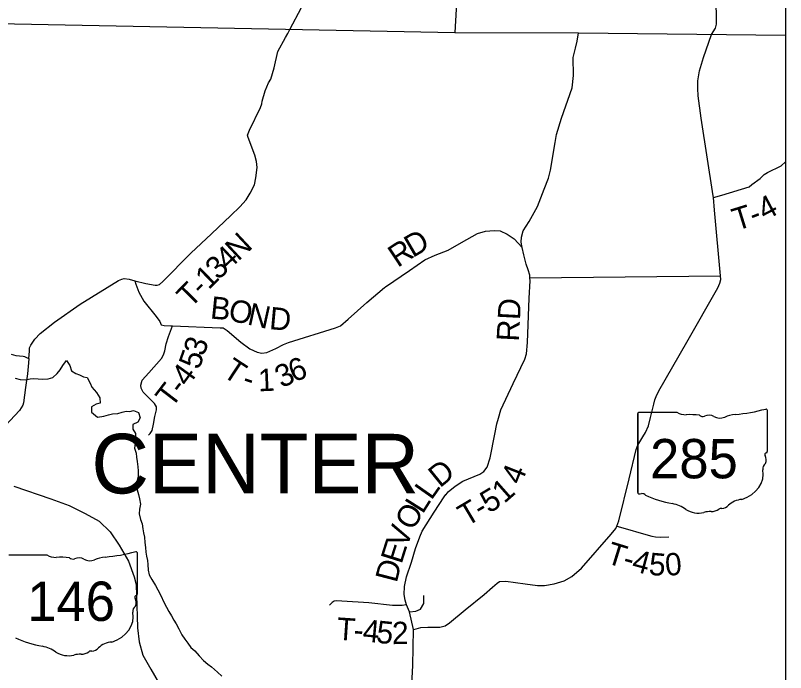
# Model space of a CAD drawing. Extents: x -22 to 431, y -18 to 160.
# Drawn here: x -3.877 to -1.919, y 15.371 to 17.042 of the extents above; entities that cross this region are included whole.
import ezdxf

# ---------------------------------------------------------------- set-up
doc = ezdxf.new("R2010")
doc.units = 0
for name, color, linetype in [('GM_X_Adjacent_County_Text', 7, 'Continuous'), ('GM_X_Airport_Location_Class_2', 7, 'Continuous'), ('GM_X_City_Street_Text', 7, 'Continuous'), ('GM_X_County_Road', 7, 'Continuous'), ('GM_X_County_Road_Text', 7, 'Continuous'), ('GM_X_Major_River_Text', 7, 'Continuous'), ('GM_X_Minor_River', 7, 'Continuous'), ('GM_X_Minor_River_Text', 7, 'Continuous'), ('GM_X_Rail_Line', 7, 'Continuous'), ('GM_X_Section', 7, 'Continuous')]:
    doc.layers.add(name, color=color, linetype=linetype)

msp = doc.modelspace()

# ---------------------------------------------------------------- linework, layer by layer
at = {"layer": 'GM_X_Adjacent_County_Text'}
msp.add_lwpolyline([(-3.888, 16.1801), (-3.8762, 16.1772), (-3.8568, 16.1754), (-3.8538, 16.1747), (-3.8485, 16.1717), (-3.8431, 16.1694), (-3.8434, 16.158), (-3.8466, 16.1307), (-3.8513, 16.0957), (-3.8563, 16.0566), (-3.8578, 16.0505), (-3.8664, 16.0371), (-3.9018, 15.9989)], dxfattribs=at)
at = {"layer": 'GM_X_Airport_Location_Class_2'}
for p, q in [((-1.9656, 16.0375), (-1.9656, 15.9328)), ((-2.2951, 16.0291), (-2.2951, 15.829)), ((-2.2951, 15.829), (-2.2951, 16.0291)), ((-2.2951, 15.829), (-2.2951, 16.0291)), ((-2.2919, 16.0325), (-2.1954, 16.0325)), ((-1.9656, 15.9328), (-1.9656, 15.9328)), ((-3.8933, 15.6699), (-3.7968, 15.6699)), ((-3.567, 15.6749), (-3.567, 15.5702)), ((-3.567, 15.5702), (-3.567, 15.5702))]:
    msp.add_line(p, q, dxfattribs=at)
for centre, major_axis, start_param, end_param in [((-2.083, 16.3054), (0.3495, 0), 4.814394, 5.042369), ((-1.9692, 16.0379), (0.00367, 0), 6.141152, 7.989035), ((-2.2914, 16.0295), (0.00382, 0), 1.712693, 3.28349), ((-2.1724, 16.0558), (0.037, 0), 4.042523, 4.731795), ((-2.1601, 15.9202), (0.133, 0), 1.404758, 1.657858), ((-2.1299, 16.0306), (0.0107, 0), 3.836095, 5.185415), ((-2.1142, 16.0074), (0.0222, 0), 0.950623, 2.079405), ((-2.0856, 16.0392), (0.0267, 0), 4.081561, 5.145723), ((-2.0384, 15.9714), (0.0703, 0), 1.699011, 2.107814), ((-1.9664, 15.9251), (0.00568, 0), 1.883978, 3.671073), ((-2.0025, 15.9119), (0.0341, 0), 5.934695, 6.695948), ((-1.9695, 15.9324), (0.00393, 0), 5.05454, 6.418171), ((-1.9524, 15.889), (0.0248, 0), 2.387724, 3.262537), ((-2.0634, 15.8757), (0.0874, 0), 5.101752, 6.440018), ((-2.2913, 15.8285), (0.00385, 0), 3.00124, 4.508301), ((-2.2907, 15.849), (0.0294, 0), 4.665946, 4.897461), ((-2.2847, 15.8174), (0.0106, 0), 0.519207, 1.627899), ((-2.1509, 15.9972), (0.2524, 0), 4.195997, 4.488961), ((-2.2262, 15.7391), (0.079, 0), 0.823519, 1.323587), ((-2.0265, 15.7728), (0.0479, 0), 1.647645, 2.488434), ((-2.1407, 15.8164), (0.0501, 0), 4.026481, 4.996735), ((-2.1118, 15.7473), (0.0412, 0), 1.495662, 1.94098), ((-2.1081, 15.8015), (0.0267, 0), 4.691044, 5.507374), ((-2.084, 15.7821), (0.00752, 0), 1.147584, 2.315152), ((-2.0872, 15.8096), (0.0282, 0), 4.937069, 5.64225), ((-3.7738, 15.6932), (0.037, 0), 4.042523, 4.731795), ((-3.7615, 15.5576), (0.133, 0), 1.404758, 1.657858), ((-3.7313, 15.668), (0.0107, 0), 3.836095, 5.185415), ((-3.7156, 15.6448), (0.0222, 0), 0.950623, 2.079405), ((-3.6398, 15.6088), (0.0703, 0), 1.699011, 2.107814), ((-3.6844, 15.9428), (0.3495, 0), 4.814394, 5.042369), ((-3.5706, 15.6753), (0.00367, 0), 6.141152, 7.989035), ((-3.687, 15.6765), (0.0267, 0), 4.081561, 5.145723), ((-3.5678, 15.5625), (0.00568, 0), 1.883978, 3.671073), ((-3.5709, 15.5698), (0.00393, 0), 5.05454, 6.418171), ((-3.6039, 15.5493), (0.0341, 0), 5.934695, 6.695948), ((-3.5538, 15.5264), (0.0248, 0), 2.387724, 3.262537), ((-3.6648, 15.5131), (0.0874, 0), 5.101752, 6.440018), ((-3.7523, 15.6346), (0.2524, 0), 4.195997, 4.488961), ((-3.6279, 15.4102), (0.0479, 0), 1.647645, 2.488434), ((-3.8276, 15.3765), (0.079, 0), 0.823519, 1.323587), ((-3.6886, 15.447), (0.0282, 0), 4.937069, 5.64225), ((-3.7421, 15.4538), (0.0501, 0), 4.026481, 4.996735), ((-3.7132, 15.3846), (0.0412, 0), 1.495662, 1.94098), ((-3.7095, 15.4388), (0.0267, 0), 4.691044, 5.507374), ((-3.6854, 15.4195), (0.00752, 0), 1.147584, 2.315152)]:
    msp.add_ellipse(centre, major_axis=major_axis, ratio=0.8, start_param=start_param, end_param=end_param, dxfattribs=at)
at = {"layer": 'GM_X_County_Road'}
msp.add_lwpolyline([(-2.5693, 16.3746), (-2.0844, 16.3793)], dxfattribs=at)
at = {"layer": 'GM_X_Major_River_Text'}
for p, q in [((-2.7468, 17.2227), (-2.7601, 16.9978)), ((-4.7644, 17.0381), (-2.7601, 16.9978)), ((-2.7601, 16.9978), (-2.4458, 16.9972)), ((-2.4458, 16.9972), (-1.9192, 16.991))]:
    msp.add_line(p, q, dxfattribs=at)
at = {"layer": 'GM_X_Minor_River'}
for points in [[(-3.8776, 16.1191), (-3.8647, 16.1158), (-3.8525, 16.1152), (-3.8397, 16.1176), (-3.8299, 16.1188), (-3.8189, 16.1174), (-3.8075, 16.1168), (-3.7939, 16.1177), (-3.7818, 16.1212), (-3.7705, 16.1312), (-3.7634, 16.1407), (-3.7564, 16.1518), (-3.7474, 16.164), (-3.7386, 16.1512)], [(-3.7386, 16.1512), (-3.7343, 16.1376), (-3.7236, 16.1309), (-3.7137, 16.128), (-3.7042, 16.1231), (-3.6947, 16.1213), (-3.6866, 16.107), (-3.6823, 16.0964), (-3.6712, 16.0825), (-3.6627, 16.0693), (-3.6618, 16.056), (-3.6717, 16.0529), (-3.6833, 16.0467), (-3.6832, 16.033), (-3.6683, 16.0203), (-3.6524, 16.0227), (-3.64, 16.0263), (-3.6298, 16.0286), (-3.6169, 16.0299), (-3.6056, 16.0331), (-3.5957, 16.0351), (-3.5863, 16.0348), (-3.5764, 16.0368), (-3.5643, 16.0323), (-3.5596, 16.0183), (-3.5659, 16.0077), (-3.5784, 16.0015), (-3.5786, 15.9901), (-3.5713, 15.9788), (-3.5708, 15.9636), (-3.5729, 15.9541), (-3.5739, 15.9416), (-3.5696, 15.9287), (-3.5688, 15.9185), (-3.5675, 15.9071), (-3.5659, 15.8942), (-3.565, 15.8836), (-3.5649, 15.8699), (-3.5678, 15.8593), (-3.5703, 15.8445), (-3.564, 15.8233), (-3.5616, 15.8123), (-3.5592, 15.7987), (-3.5617, 15.7861), (-3.5627, 15.7743), (-3.5592, 15.7599), (-3.5549, 15.7494), (-3.5529, 15.7365), (-3.5513, 15.7263), (-3.5492, 15.7149), (-3.5476, 15.7012), (-3.5463, 15.6887), (-3.5454, 15.677), (-3.5438, 15.6668), (-3.5414, 15.6561), (-3.5402, 15.6455), (-3.5393, 15.6315), (-3.5365, 15.619), (-3.5303, 15.6073), (-3.5207, 15.5918), (-3.5153, 15.5813), (-3.5068, 15.565), (-3.5002, 15.5518), (-3.4925, 15.5375), (-3.4867, 15.5265), (-3.4801, 15.5148), (-3.474, 15.5043), (-3.4682, 15.4945), (-3.4612, 15.482), (-3.4535, 15.4669), (-3.4462, 15.4556), (-3.4389, 15.4458), (-3.4308, 15.4345), (-3.4205, 15.4263), (-3.4094, 15.4138), (-3.3987, 15.4018), (-3.388, 15.3924), (-3.3784, 15.3853), (-3.3635, 15.3718), (-3.3524, 15.3613)]]:
    msp.add_lwpolyline(points, dxfattribs=at)
at = {"layer": 'GM_X_Minor_River_Text'}
for points in [[(-3.1848, 16.9959), (-3.1793, 17.0062), (-3.1497, 17.0618), (-3.075, 17.216), (-3.0391, 17.2815), (-3.0388, 17.2822)], [(-3.5737, 16.3665), (-3.5456, 16.3598), (-3.5213, 16.3562), (-3.5164, 16.3562), (-3.5103, 16.3578), (-3.502, 16.3647), (-3.4312, 16.4373), (-3.3788, 16.4863), (-3.3291, 16.5325), (-3.3065, 16.5547), (-3.2903, 16.5727), (-3.2798, 16.5894), (-3.2694, 16.6112), (-3.2657, 16.6286), (-3.2628, 16.6549), (-3.2641, 16.6704), (-3.268, 16.6859), (-3.285, 16.7314), (-3.287, 16.7374), (-3.2821, 16.7496), (-3.2541, 16.8075), (-3.2504, 16.817), (-3.2497, 16.8235), (-3.2423, 16.8497), (-3.2333, 16.8703), (-3.2277, 16.8798), (-3.2188, 16.9083), (-3.21, 16.9498), (-3.1905, 16.9852), (-3.1848, 16.9959)], [(-2.5891, 16.4516), (-2.5911, 16.4648), (-2.5905, 16.4777), (-2.586, 16.4941), (-2.571, 16.5177), (-2.5501, 16.5558), (-2.5329, 16.6), (-2.5221, 16.6278), (-2.517, 16.6479), (-2.505, 16.7186), (-2.5013, 16.7391), (-2.4887, 16.7802), (-2.4616, 16.8575), (-2.458, 16.8886), (-2.4591, 16.9345), (-2.4533, 16.9584), (-2.449, 16.9759), (-2.4458, 16.9972)], [(-2.1027, 16.5788), (-2.0814, 16.585), (-2.0121, 16.6059), (-2.0049, 16.6113), (-1.9838, 16.627), (-1.974, 16.637), (-1.965, 16.6423), (-1.9306, 16.6589), (-1.9192, 16.6694)], [(-2.9363, 16.3515), (-2.9361, 16.3517), (-2.8751, 16.393), (-2.8359, 16.4198), (-2.8102, 16.4318), (-2.7769, 16.4449), (-2.7433, 16.4641), (-2.7024, 16.4868), (-2.6824, 16.493), (-2.6596, 16.4947), (-2.6445, 16.4937), (-2.6266, 16.4855), (-2.609, 16.4734), (-2.5891, 16.4516)], [(-2.7825, 15.8234), (-2.7823, 15.8236), (-2.7765, 15.8302), (-2.7592, 15.8448), (-2.7396, 15.8571), (-2.6965, 15.8752), (-2.6863, 15.8821), (-2.6776, 15.8928), (-2.6698, 15.9172), (-2.6581, 15.9769), (-2.653, 16.0035), (-2.6489, 16.0176), (-2.643, 16.0389), (-2.6113, 16.1059), (-2.5821, 16.1676), (-2.5777, 16.1813), (-2.5756, 16.2102), (-2.5708, 16.3226), (-2.5688, 16.367), (-2.5693, 16.3746), (-2.5697, 16.3811), (-2.5736, 16.3947), (-2.579, 16.4095), (-2.5848, 16.4326), (-2.5891, 16.4516)], [(-3.8431, 16.1694), (-3.841, 16.1884), (-3.841, 16.1964), (-3.8381, 16.2033), (-3.8276, 16.2185), (-3.8136, 16.2327), (-3.7774, 16.2618), (-3.7121, 16.3074), (-3.6151, 16.3673), (-3.6067, 16.3712), (-3.6007, 16.3727), (-3.5874, 16.3713), (-3.5737, 16.3665)], [(-3.5737, 16.3665), (-3.5706, 16.3585), (-3.5636, 16.3384), (-3.5502, 16.315), (-3.5192, 16.2765), (-3.51, 16.2633), (-3.5065, 16.2546), (-3.4989, 16.2535), (-3.482, 16.2524)], [(-3.482, 16.2524), (-3.4776, 16.2521), (-3.3566, 16.2476), (-3.349, 16.2473), (-3.3387, 16.2409), (-3.3036, 16.2112), (-3.2807, 16.1943), (-3.2621, 16.1857), (-3.2507, 16.1831), (-3.2382, 16.1847), (-3.2151, 16.1951), (-3.1958, 16.2047), (-3.183, 16.2101), (-3.063, 16.2474), (-3.0509, 16.2528), (-3.0313, 16.2693), (-2.9838, 16.3117), (-2.9386, 16.35), (-2.9363, 16.3515)], [(-3.539, 15.9745), (-3.5344, 15.9783), (-3.5296, 15.9863), (-3.5259, 16.0027), (-3.5226, 16.0221), (-3.5182, 16.0392), (-3.5183, 16.0468), (-3.5232, 16.0547), (-3.5519, 16.0841), (-3.5573, 16.0936), (-3.5585, 16.1012), (-3.5548, 16.1141), (-3.5379, 16.1325), (-3.5059, 16.1691), (-3.5003, 16.179), (-3.4969, 16.1886), (-3.4936, 16.2068), (-3.4881, 16.2251), (-3.4776, 16.2521)], [(-2.8646, 15.4806), (-2.875, 15.5254), (-2.8829, 15.5432), (-2.886, 15.5553), (-2.8888, 15.5693), (-2.8882, 15.5894), (-2.8827, 15.6145), (-2.8704, 15.6519), (-2.8601, 15.6861), (-2.8489, 15.7162), (-2.8426, 15.7307), (-2.8122, 15.7787), (-2.7874, 15.8176), (-2.7825, 15.8234)], [(-2.3484, 15.7427), (-2.3271, 15.737), (-2.2807, 15.7236), (-2.259, 15.7177), (-2.2499, 15.7159), (-2.2362, 15.7148), (-2.2158, 15.7161)], [(-2.875, 15.5254), (-2.8593, 15.5273), (-2.8473, 15.5324), (-2.8388, 15.5461), (-2.8388, 15.5665)], [(-2.8829, 15.5432), (-2.8935, 15.5412), (-2.9019, 15.5411), (-2.9182, 15.5414), (-2.9782, 15.5482), (-3.0476, 15.5522), (-3.0609, 15.5529), (-3.0666, 15.5521), (-3.0715, 15.549), (-3.0787, 15.5418)]]:
    msp.add_lwpolyline(points, dxfattribs=at)
at = {"layer": 'GM_X_Rail_Line'}
for points in [[(-2.8698, 15.3253), (-2.8669, 15.3886), (-2.8646, 15.4806), (-2.8582, 15.4822), (-2.8461, 15.4857), (-2.8286, 15.4866), (-2.7979, 15.4864), (-2.7915, 15.4876), (-2.7846, 15.4895), (-2.7733, 15.4976), (-2.7334, 15.5305), (-2.6855, 15.5696), (-2.6644, 15.5884), (-2.6527, 15.5979), (-2.6463, 15.6022), (-2.6307, 15.603), (-2.581, 15.5965), (-2.5498, 15.5922), (-2.5324, 15.592), (-2.5074, 15.5963), (-2.482, 15.6041), (-2.4627, 15.6152), (-2.4379, 15.6359), (-2.3626, 15.7226), (-2.351, 15.7375), (-2.3484, 15.7427), (-2.3428, 15.757), (-2.317, 15.8638), (-2.299, 15.938), (-2.2949, 15.9487), (-2.29, 15.9578), (-2.2818, 15.9704), (-2.2754, 15.9815), (-2.2675, 15.9982), (-2.2624, 16.0192), (-2.2543, 16.053), (-2.2517, 16.064), (-2.2484, 16.0724), (-2.2413, 16.0873), (-2.1701, 16.2108), (-2.0914, 16.3488), (-2.0866, 16.3609), (-2.084, 16.3701), (-2.0844, 16.3793), (-2.0997, 16.5465), (-2.1027, 16.5788), (-2.103, 16.5825), (-2.1336, 16.7805), (-2.1413, 16.837), (-2.1425, 16.8559), (-2.1419, 16.8749), (-2.1379, 16.9007), (-2.1276, 16.9342), (-2.1078, 16.9932), (-2.0974, 17.0092), (-2.0948, 17.0191), (-2.0945, 17.0301), (-2.0971, 17.1815)], [(-3.8813, 15.8449), (-3.787, 15.8126), (-3.74, 15.7954), (-3.6994, 15.7752), (-3.6638, 15.756), (-3.6357, 15.7287), (-3.6135, 15.6948), (-3.5898, 15.6545), (-3.5751, 15.6141), (-3.5702, 15.5944), (-3.5686, 15.5397), (-3.5675, 15.5146), (-3.5663, 15.4846), (-3.5623, 15.4489), (-3.5531, 15.4149), (-3.5328, 15.3795), (-3.5105, 15.341), (-3.4543, 15.2891), (-3.3469, 15.2432), (-3.2812, 15.216), (-3.2811, 15.216)]]:
    msp.add_lwpolyline(points, dxfattribs=at)
at = {"layer": 'GM_X_Section'}
msp.add_line((-1.9192, 20.9345), (-1.9192, 14.1345), dxfattribs=at)

# ---------------------------------------------------------------- texts
at = {"layer": 'GM_X_Airport_Location_Class_2'}
for s, p in [('285', (-2.2637, 15.8647)), ('146', (-3.847, 15.5021))]:
    msp.add_text(s, height=0.1, dxfattribs=at).set_placement(p)
at = {"layer": 'GM_X_City_Street_Text'}
for s, height, rotation, p in [('4', 0.0568, 27.7307, (-1.9717, 16.5189)), ('T', 0.0568, 17.2341, (-2.0445, 16.4936)), ('-', 0.0568, 21.2035, (-1.9999, 16.5076)), ('N', 0.0568, 43.1296, (-3.3106, 16.4152)), ('D', 0.0568, 30.2478, (-2.867, 16.4246)), ('R', 0.0568, 33.506, (-2.9052, 16.3993)), ('4', 0.0568, 43.3954, (-3.3359, 16.3912)), ('3', 0.0568, 44.0616, (-3.361, 16.3669)), ('1', 0.0568, 44.5879, (-3.3858, 16.3425)), ('T', 0.0568, 45.6182, (-3.4318, 16.2957)), ('-', 0.0568, 45.276, (-3.4021, 16.326)), ('B', 0.0568, 354.2335, (-3.3832, 16.2713)), ('O', 0.0568, 347.6727, (-3.3385, 16.2669)), ('N', 0.0568, 347.5648, (-3.2897, 16.2562)), ('RD', 0.05682, 87.0641, (-2.5972, 16.2116)), ('D', 0.0568, 354.853, (-3.2331, 16.2442)), ('3', 0.0568, 71.3433, (-3.398, 16.1727)), ('5', 0.0568, 70.3711, (-3.4101, 16.1387)), ('T', 0.0568, 326.4062, (-3.3536, 16.1268)), ('6', 0.0568, 21.7676, (-3.1694, 16.108)), ('4', 0.0568, 54.09, (-3.4388, 16.0949)), ('3', 0.0568, 25.6561, (-3.2, 16.0932)), ('1', 0.0568, 2.4177, (-3.2592, 16.0857)), ('-', 0.0568, 341.7017, (-3.3034, 16.0961)), ('T', 0.0568, 52.4761, (-3.4799, 16.0412)), ('-', 0.0568, 52.637, (-3.4539, 16.0751)), ('D', 0.0568, 38.9977, (-2.7979, 15.839)), ('4', 0.0568, 68.4569, (-2.5914, 15.846)), ('1', 0.0568, 41.3287, (-2.6344, 15.7991)), ('L', 0.0568, 54.8823, (-2.8195, 15.8073)), ('5', 0.0568, 31.0893, (-2.6733, 15.7745)), ('L', 0.0568, 57.8279, (-2.8417, 15.772)), ('T', 0.0568, 30.7219, (-2.7302, 15.7407)), ('O', 0.0568, 59.571, (-2.8668, 15.7292)), ('-', 0.0568, 30.7706, (-2.6937, 15.7624)), ('V', 0.0568, 69.8473, (-2.8829, 15.6847)), ('E', 0.0568, 72.488, (-2.8955, 15.6449)), ('T', 0.0568, 342.8743, (-2.3781, 15.6501)), ('4', 0.0568, 344.8227, (-2.313, 15.6307)), ('5', 0.0568, 355.0643, (-2.2684, 15.6196)), ('0', 0.0568, 4.3917, (-2.2234, 15.6166)), ('D', 0.0568, 75.3948, (-2.9079, 15.5972)), ('-', 0.0568, 344.3586, (-2.336, 15.6372)), ('T', 0.0568, 356.2216, (-3.0612, 15.4546)), ('4', 0.0568, 354.6897, (-2.9959, 15.4501)), ('5', 0.0568, 354.2397, (-2.9612, 15.4469)), ('2', 0.0568, 0.51, (-2.9196, 15.443)), ('-', 0.0568, 355.8282, (-3.0189, 15.4518))]:
    msp.add_text(s, height=height, rotation=rotation, dxfattribs=at).set_placement(p)
at = {"layer": 'GM_X_County_Road_Text'}
msp.add_text('CENTER', height=0.15152, rotation=0, dxfattribs=at).set_placement((-3.6838, 15.8263))

doc.saveas('drawing.dxf')
